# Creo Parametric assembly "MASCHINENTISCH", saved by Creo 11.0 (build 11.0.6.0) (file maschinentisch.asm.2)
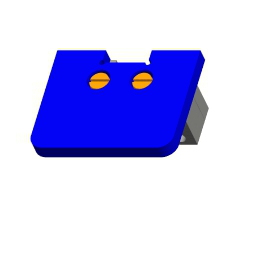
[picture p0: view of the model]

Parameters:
  ERSTELLER = "ARINDA"
  BENENNUNG = "XXX"
  TEILETYP = "K"

Other parameters: MASSE

Created from: ARINDA.ASM

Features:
  1. coordinate system "ACS0"
  2. datum plane "ADTM1", "A_RECHTS_Y-Z"
  3. datum plane "ADTM2", "A_OBEN_X-Z"
  4. datum plane "ADTM3", "A_VORNE_X-Y"
  5. datum axis "AA_X"
  6. datum axis "AA_2"
  7. datum axis "AA_Z"
  8. datum point "APNT0"
  9. component "MASCHINENTISCH_NEU", "MASCHINENTISCH.PRT"
  10. component "KONSOLE", "UNTERBAU_MASCHINENTISCH.PRT"
  11. pattern "Muster 1"
  12. component "ISO1207", "EI1207M4X5V4.PRT"
  13. component "ISO1207", "EI1207M4X5V4.PRT"
  14. component "FÜHRUNG_MASCHINENTISCH"
  15. component "FÜHRUNG_MASCHINENTISCH"
  16. component "ISO1207", "EI1207M4X5V4.PRT"
  17. component "ISO1207", "EI1207M4X5V4.PRT"
  18. pattern "Muster 2"
  19. component "ISO2338", "ISO2338A4X10.PRT"
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
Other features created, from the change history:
  datum axis "AA_1"
  datum plane "ADTM1"
  pattern "Muster 1"
  component "EI1207M4X5V4.PRT"
  pattern "Muster 2"
  component "ISO2338A4X10.PRT"
  component "ISO2338", "ISO2338A4X10.PRT" (3 times)
  pattern "Muster 3"

Other named items: AA_Y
